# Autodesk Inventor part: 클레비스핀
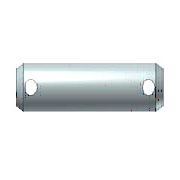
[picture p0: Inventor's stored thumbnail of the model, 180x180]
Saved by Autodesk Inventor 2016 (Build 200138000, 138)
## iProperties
IsCustomPart: 1
Created: 2012-02
Part Number: 클레비스핀
Material: 강철
Description: 머리가 없는 클레비스 핀 B
Document SubType Name: Modeling
Standard: ISO 2340
Designer: mduedu
Standard Revision: Second edition 1986-11-01
Standards Organization: ISO
Language: ko-KR
Size Designation: B - 8 x 45
Categories: <MemberInstance><Categories><Category DisplayName="조임쇠" InternalName="e4da775c-781d-43d5-af7c-5136215cf5a6" Mnemonic="FSTN"><Category DisplayName="핀" InternalNa
Density: 7.85 g/cm^3
Appearance: 강철
Author: mduedu
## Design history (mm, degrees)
sketch "스케치1"
  geometry: L1 (-4.5, 0)-(-4.5, 4); L2 (-4.5, 4)-(40.5, 4); L3 (40.5, 4)-(40.5, 0); L4 (-4.5, 0)-(40.5, 0); L5 (0, -1.46)-(0, 3.16) reference; L6 (-6.4, 0)-(18.8, 0) reference; C1 r 1 at (-1, 0); C2 r 1 at (37, 0)
  constraints: 8 end point, 2 centre point, 2 perpendicular, 2 point on line, 1 collinear, 1 parallel, 1 tangent, 1 vertical
  dimensions: "d0" = 8 diameter of L2 L4 (= NND); "d1" = 45 distance of L1.end L2.end (= NLG); "d2" = 3.5 distance from line of L1 C1.centre (= DIST1); "d3" = 3.5 distance from line of L3 C2.centre (= DIST2); "d4" = 2 diameter of C1 (= BOR1); "d5" = 2 diameter of C2 (= BOR2)
revolve "본체" stored, may be unused: angle "d7" = 90 deg
extrude "구멍1" cut sketch "스케치1" taper "d6" = 0 deg; stored distance "d8" = 10
extrude "구멍2" cut sketch "스케치1" taper "d13" = 0 deg; stored distance "d14" = 10
workaxis "Work Axis1"
workaxis "Work Axis2"
workplane "Work Plane1"
node "작업 평면5"
body "Solid1"
chamfer "모따기2" distance "d9" = 2 (= PHH2); stored, may be unused: angle "d10" = 30 deg (= FAWI2), second distance "d40" = 2 (= PHH2)
chamfer "모따기1" distance "d11" = 2 (= PHH1); stored, may be unused: angle "d12" = 30 deg (= FAWI1), second distance "d41" = 2 (= PHH1)
other parameters: "NLG" = 45 [user parameter; used in 1 equation term], "NND" = 8 [user parameter; used in 1 equation term], "PHH1" = 2 [user parameter; used in 3 equation terms], "PHH2" = 2 (= PHH1) [user parameter; used in 2 equation terms], "FAWI1" = 30 deg [user parameter; used in 1 equation term], "FAWI2" = 30 deg [user parameter; used in 1 equation term], "DIST1" = 3.5 [user parameter; used in 4 equation terms], "DIST2" = 3.5 (= DIST1) [user parameter; used in 1 equation term], "BOR1" = 2 [user parameter; used in 4 equation terms], "BOR2" = 2 (= BOR1) [user parameter; used in 1 equation term], "d15" = 0, "d42" = 0, "d43" = 0, "d44" = -4.5 (= -0.5 x BOR1 - DIST1), "d45" = -4.5 (= -0.5 x BOR1 - DIST1), "d47" = 0, "d48" = 0, "d49" = 0, "d50" = 0, "d51" = 0, "d52" = 0
